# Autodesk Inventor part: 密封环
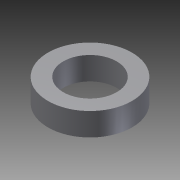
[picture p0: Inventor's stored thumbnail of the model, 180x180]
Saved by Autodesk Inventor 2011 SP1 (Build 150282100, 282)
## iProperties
Created: 2013-12
Part Number: 密封环
Document SubType Name: Modeling
Designer: Administrator
Density: 1 g/cm^3
Author: Administrator
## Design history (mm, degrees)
sketch "草图1"
  geometry: C1 r 7 at (0, 0); C2 r 11 at (0, 0); 1 further point
  constraints: 2 centre point, 2 coincident
  dimensions: "d0" = 14 diameter of C1; "d1" = 22 diameter of C2
extrude "拉伸1" new body sketch "草图1" distance "d2" = 6; taper "d3" = 0 deg
node "实体1"
